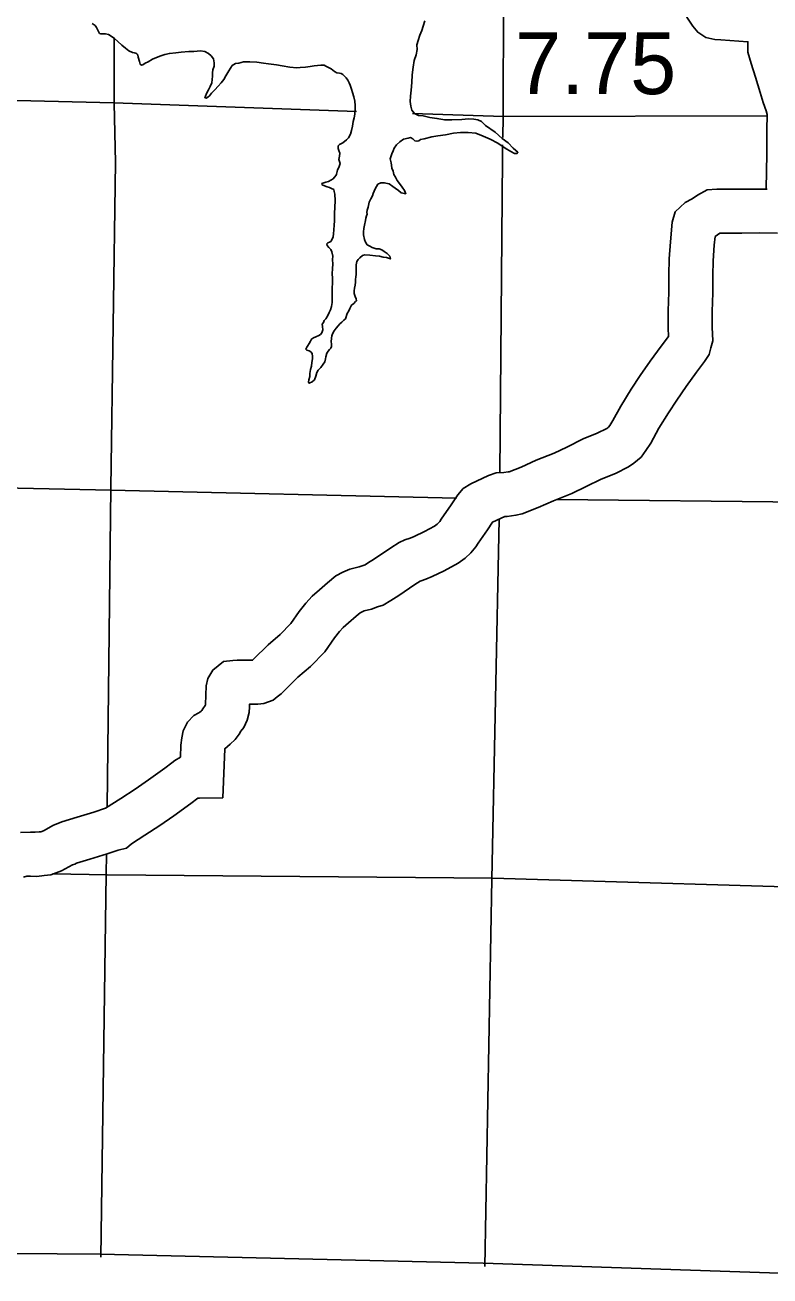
# Model space of a CAD drawing. Extents: x 77230 to 630905, y 790554 to 1662844.
# Drawn here: x 274501 to 284669, y 1532754 to 1549835 of the extents above; entities that cross this region are included whole.
import ezdxf

# ---------------------------------------------------------------- set-up
doc = ezdxf.new("R2010")
doc.units = 0
for name, color, linetype in [('Level 16', 7, 'Continuous'), ('Level 17', 7, 'Continuous'), ('Level 18', 7, 'Continuous'), ('Level 22', 7, 'Continuous'), ('Level 31', 7, 'Continuous')]:
    doc.layers.add(name, color=color, linetype=linetype)

msp = doc.modelspace()

# ---------------------------------------------------------------- linework, layer by layer
at = {"layer": 'Level 16'}
for points in [[(281022, 1548297), (281027, 1548585), (281030, 1550183)], [(275718, 1549654), (275717, 1548768), (275734, 1547959)], [(279023, 1548655), (275711, 1548770), (270417, 1548899), (265076, 1549037), (261346, 1549057)], [(284632, 1548594), (281033, 1548585), (279790, 1548628)], [(281017, 1548018), (281020, 1548199)], [(281017, 1548018), (280981, 1543718)], [(275734, 1547959), (275672, 1543517), (275621, 1539160)], [(265041, 1543701), (270397, 1543598), (275673, 1543482), (280389, 1543376)], [(281762, 1543355), (285132, 1543322)], [(280972, 1543087), (280872, 1538172), (280775, 1532884)], [(275613, 1538514), (275610, 1538239), (275534, 1533012)], [(274881, 1538244), (275622, 1538233), (280881, 1538186), (286111, 1538030), (287282, 1538032)]]:
    msp.add_lwpolyline(points, dxfattribs=at)
at = {"layer": 'Level 17'}
for points in [[(279957, 1549891), (279937, 1549818), (279916, 1549760), (279892, 1549698), (279865, 1549624), (279851, 1549564), (279853, 1549500), (279838, 1549427), (279814, 1549351), (279799, 1549261), (279787, 1549155), (279782, 1549051), (279771, 1548943), (279763, 1548865), (279756, 1548792), (279766, 1548727), (279782, 1548671), (279817, 1548625), (279871, 1548601), (279937, 1548594), (280027, 1548570), (280123, 1548559), (280229, 1548539), (280328, 1548542), (280462, 1548543), (280554, 1548552), (280626, 1548548), (280680, 1548538), (280732, 1548519), (280788, 1548463), (280919, 1548372)], [(276012, 1549450), (275992, 1549456), (275968, 1549460), (275918, 1549483), (275872, 1549517), (275824, 1549561), (275768, 1549609), (275720, 1549650), (275677, 1549684), (275641, 1549706), (275599, 1549716), (275563, 1549715), (275535, 1549713), (275519, 1549719), (275505, 1549747), (275475, 1549803), (275459, 1549827), (275419, 1549854)], [(278786, 1547998), (278795, 1548042), (278797, 1548086), (278785, 1548122), (278775, 1548150), (278775, 1548174), (278776, 1548186), (278794, 1548202), (278838, 1548224), (278890, 1548266), (278914, 1548293), (278945, 1548345), (278957, 1548395), (278971, 1548455), (278982, 1548517), (278994, 1548569), (279002, 1548619), (279007, 1548683), (279005, 1548735), (279001, 1548795), (278990, 1548855), (278972, 1548913), (278958, 1548961), (278941, 1549013), (278923, 1549045), (278907, 1549083), (278883, 1549113), (278863, 1549135), (278839, 1549157), (278817, 1549171), (278793, 1549176), (278759, 1549182), (278725, 1549202), (278680, 1549236), (278644, 1549253), (278608, 1549275), (278582, 1549285), (278538, 1549287), (278492, 1549280), (278446, 1549276), (278393, 1549270), (278327, 1549259), (278255, 1549255), (278209, 1549251), (278117, 1549258), (278009, 1549279), (277935, 1549289), (277823, 1549306), (277755, 1549314), (277663, 1549327), (277571, 1549330), (277485, 1549330), (277421, 1549315), (277374, 1549307), (277328, 1549281), (277284, 1549208), (277241, 1549140), (277213, 1549092), (277179, 1549046), (277138, 1549001), (277092, 1548949), (277048, 1548905), (277017, 1548868), (276995, 1548848), (276973, 1548838), (276957, 1548842), (276963, 1548864), (276980, 1548898), (277004, 1548948), (277028, 1548995), (277050, 1549047), (277057, 1549089), (277061, 1549137), (277061, 1549183), (277066, 1549225), (277082, 1549271), (277082, 1549319), (277074, 1549373), (277043, 1549413), (277007, 1549445), (276955, 1549472), (276897, 1549480), (276805, 1549475), (276735, 1549475), (276634, 1549462), (276558, 1549454), (276472, 1549447), (276410, 1549433), (276356, 1549416), (276296, 1549392), (276239, 1549368), (276181, 1549333), (276141, 1549313), (276109, 1549293), (276089, 1549288), (276073, 1549300), (276061, 1549338), (276047, 1549396), (276039, 1549426), (276028, 1549442), (276012, 1549450)], [(280919, 1548372), (281015, 1548287), (281095, 1548225), (281162, 1548155), (281200, 1548120), (281228, 1548098), (281216, 1548080), (281182, 1548079), (281132, 1548107), (281056, 1548155), (280956, 1548220), (280849, 1548275), (280753, 1548319), (280655, 1548358), (280549, 1548367), (280443, 1548367), (280348, 1548356), (280240, 1548333), (280134, 1548321), (280052, 1548308), (279948, 1548281), (279899, 1548273), (279875, 1548253), (279849, 1548247), (279823, 1548253), (279809, 1548266), (279793, 1548282), (279763, 1548298), (279729, 1548290), (279669, 1548274), (279615, 1548239), (279569, 1548199), (279538, 1548151), (279524, 1548118), (279506, 1548076), (279483, 1548006)], [(278786, 1547998), (278802, 1547942), (278782, 1547888), (278768, 1547857), (278761, 1547835), (278753, 1547799), (278749, 1547785), (278727, 1547755), (278705, 1547733), (278675, 1547715), (278641, 1547698), (278606, 1547690), (278578, 1547678), (278554, 1547670), (278558, 1547652), (278588, 1547640), (278624, 1547624), (278658, 1547616), (278684, 1547602), (278714, 1547587), (278722, 1547563), (278728, 1547525), (278729, 1547493), (278733, 1547469), (278735, 1547444), (278733, 1547414), (278729, 1547364), (278728, 1547324), (278726, 1547282), (278724, 1547248), (278724, 1547214), (278725, 1547160), (278719, 1547102), (278717, 1547036), (278712, 1546982), (278706, 1546941), (278694, 1546911), (278674, 1546881), (278656, 1546869), (278635, 1546861), (278621, 1546849), (278623, 1546825), (278647, 1546797), (278677, 1546771), (278689, 1546737), (278700, 1546679), (278698, 1546635), (278700, 1546569), (278699, 1546509), (278695, 1546439), (278697, 1546378), (278698, 1546310), (278692, 1546244), (278693, 1546174), (278695, 1546096), (278691, 1546044), (278682, 1545992), (278670, 1545947), (278650, 1545909), (278629, 1545861), (278605, 1545825), (278585, 1545799), (278573, 1545775), (278555, 1545750), (278563, 1545720), (278564, 1545674), (278554, 1545630), (278534, 1545610), (278510, 1545594), (278470, 1545577), (278440, 1545565), (278413, 1545547), (278399, 1545517), (278381, 1545487), (278357, 1545450), (278349, 1545438), (278333, 1545408), (278348, 1545396), (278378, 1545387), (278404, 1545371), (278422, 1545351), (278424, 1545307), (278426, 1545277), (278416, 1545229), (278409, 1545176), (278397, 1545132), (278389, 1545076), (278390, 1545034), (278376, 1544992), (278372, 1544960), (278380, 1544944), (278420, 1544962), (278450, 1544992), (278468, 1545039), (278485, 1545091), (278503, 1545123), (278537, 1545157), (278569, 1545204), (278592, 1545236), (278600, 1545278), (278608, 1545304)], [(278608, 1545304), (278622, 1545352), (278639, 1545382), (278655, 1545406), (278675, 1545421), (278685, 1545447), (278685, 1545483), (278681, 1545511), (278686, 1545557), (278688, 1545591), (278698, 1545617), (278720, 1545657), (278747, 1545696), (278775, 1545728), (278797, 1545754), (278825, 1545778), (278851, 1545805), (278875, 1545823), (278900, 1545895), (278920, 1545933), (278936, 1545963), (278957, 1546008), (278987, 1546032), (279013, 1546058), (279025, 1546070), (279021, 1546098), (279005, 1546130), (278994, 1546168), (278994, 1546204), (278998, 1546242), (279006, 1546284), (279012, 1546323), (279013, 1546359), (279017, 1546395), (279019, 1546429), (279021, 1546473), (279022, 1546519), (279022, 1546559), (279032, 1546605), (279050, 1546631), (279073, 1546658), (279105, 1546688), (279141, 1546696), (279207, 1546692), (279283, 1546683), (279337, 1546677), (279389, 1546666), (279433, 1546662), (279489, 1546640), (279479, 1546678), (279443, 1546714), (279405, 1546742), (279373, 1546766), (279333, 1546778), (279295, 1546781), (279241, 1546797), (279208, 1546815), (279172, 1546832), (279146, 1546870), (279136, 1546906), (279122, 1546968), (279123, 1547010), (279127, 1547055), (279133, 1547103), (279146, 1547165), (279154, 1547199), (279164, 1547229), (279172, 1547251), (279166, 1547277), (279170, 1547305), (279183, 1547347), (279197, 1547416), (279219, 1547460), (279242, 1547504), (279254, 1547532), (279268, 1547564), (279278, 1547599), (279296, 1547631), (279317, 1547661), (279357, 1547679), (279403, 1547682), (279469, 1547666), (279519, 1547632), (279552, 1547606), (279600, 1547575), (279636, 1547545), (279698, 1547531), (279680, 1547573), (279649, 1547621), (279611, 1547669), (279581, 1547711), (279557, 1547757), (279536, 1547793), (279526, 1547841), (279508, 1547881), (279502, 1547921), (279499, 1547955), (279483, 1548006)]]:
    msp.add_lwpolyline(points, dxfattribs=at)
at = {"layer": 'Level 18'}
msp.add_lwpolyline([(259715, 1533246), (264915, 1533166), (270250, 1533095), (275526, 1533052), (280755, 1532930), (286011, 1532754), (289923, 1532839)], dxfattribs=at)
at = {"layer": 'Level 22'}
for points in [[(281692, 1550514), (282374, 1550420), (282839, 1550318), (283250, 1550228), (283375, 1550200), (283479, 1550030), (283554, 1549915), (283617, 1549817), (283683, 1549737), (283792, 1549665), (283916, 1549639), (283998, 1549634), (284367, 1549607), (284368, 1549465), (284413, 1549307), (284471, 1549123), (284537, 1548914), (284578, 1548777), (284616, 1548661), (284631, 1548613), (284631, 1548591), (284628, 1548423), (284624, 1548070)], [(284618, 1547603), (284624, 1548070)], [(276622, 1539839), (276628, 1540004), (276640, 1540100), (276659, 1540198), (276718, 1540318), (276806, 1540407), (276873, 1540443), (276887, 1540452), (276904, 1540466), (276915, 1540476), (276930, 1540497), (276961, 1540544), (276965, 1540549), (276966, 1540555), (276971, 1540810), (276997, 1540912), (277062, 1541027), (277210, 1541142), (277335, 1541156), (277397, 1541162), (277607, 1541162), (277620, 1541175), (277820, 1541374), (277985, 1541513), (278127, 1541661), (278244, 1541827), (278334, 1541939), (278420, 1542037), (278522, 1542123), (278631, 1542220), (278742, 1542312), (278838, 1542362), (278935, 1542407), (279061, 1542436), (279118, 1542457), (279142, 1542465), (279176, 1542485), (279270, 1542545), (279494, 1542698), (279609, 1542769), (279685, 1542805), (279758, 1542829), (279812, 1542852), (279954, 1542920), (280092, 1542993), (280126, 1543019), (280149, 1543040), (280163, 1543057), (280181, 1543087), (280319, 1543284), (280410, 1543419), (280480, 1543506), (280585, 1543568), (280826, 1543684), (280931, 1543722), (281036, 1543725), (281095, 1543732), (281111, 1543736), (281275, 1543799), (281479, 1543892), (281723, 1543989), (281897, 1544073), (282118, 1544183), (282311, 1544260), (282441, 1544327), (282457, 1544336), (282466, 1544345), (282481, 1544366), (282526, 1544433), (282633, 1544631), (282776, 1544863), (282899, 1545049), (283033, 1545243), (283182, 1545450), (283284, 1545584), (283281, 1545699), (283281, 1545932), (283288, 1546186), (283288, 1546426), (283295, 1546644), (283310, 1546876), (283334, 1547143), (283375, 1547285), (283512, 1547413), (283606, 1547461), (283681, 1547513), (283811, 1547584), (283943, 1547595), (284047, 1547593), (284286, 1547593), (284526, 1547595), (284632, 1547594)], [(277203, 1539283), (277226, 1539954), (277302, 1540016), (277367, 1540079), (277423, 1540154), (277448, 1540191), (277487, 1540241), (277535, 1540344), (277559, 1540447), (277565, 1540526), (277566, 1540562), (277678, 1540562), (277761, 1540572), (277886, 1540615), (277944, 1540664), (277997, 1540703), (278045, 1540752), (278226, 1540932), (278396, 1541075), (278591, 1541278), (278724, 1541466), (278793, 1541552), (278842, 1541608), (278915, 1541671), (279020, 1541764), (279076, 1541809), (279104, 1541824), (279131, 1541836), (279232, 1541860), (279311, 1541889), (279390, 1541914), (279492, 1541975), (279601, 1542044), (279823, 1542195), (279896, 1542241), (279907, 1542246), (279970, 1542267), (280059, 1542305), (280224, 1542384), (280413, 1542485), (280510, 1542557), (280587, 1542628), (280656, 1542711), (280686, 1542762), (280813, 1542944), (280881, 1543045), (281048, 1543125), (281083, 1543126), (281201, 1543141), (281288, 1543162), (281507, 1543246), (281714, 1543340), (281964, 1543439), (282161, 1543534), (282363, 1543635), (282560, 1543713), (282737, 1543804), (282813, 1543851), (282911, 1543936), (282975, 1544024), (283041, 1544125), (283152, 1544330), (283282, 1544540), (283396, 1544713), (283524, 1544897), (283665, 1545093), (283775, 1545239), (283838, 1545335), (283864, 1545429), (283887, 1545523), (283881, 1545708), (283881, 1545923), (283888, 1546178), (283888, 1546415), (283895, 1546614), (283909, 1546831), (283919, 1546947), (283986, 1546994), (284042, 1546993), (284287, 1546993), (284527, 1546995), (284774, 1546994)], [(274438, 1538808), (274577, 1538815), (274641, 1538812), (274693, 1538818), (274715, 1538820), (274752, 1538833), (274890, 1538909), (274949, 1538933), (275003, 1538955), (275213, 1539019), (275440, 1539088), (275601, 1539141), (275808, 1539275), (276004, 1539403), (276185, 1539530), (276407, 1539687), (276503, 1539762), (276547, 1539793), (276624, 1539836)], [(274479, 1538200), (274525, 1538212), (274577, 1538214), (274661, 1538210), (274761, 1538221), (274851, 1538232), (274998, 1538284), (275150, 1538367), (275179, 1538379), (275205, 1538389), (275386, 1538445), (275622, 1538516), (275774, 1538566), (275884, 1538594), (275952, 1538653), (276135, 1538771), (276341, 1538906), (276530, 1539039), (276766, 1539205), (276858, 1539277), (276883, 1539280), (277203, 1539283)]]:
    msp.add_lwpolyline(points, dxfattribs=at)

# ---------------------------------------------------------------- texts
at = {"layer": 'Level 31'}
msp.add_text('7.75', height=844.8, dxfattribs=at).set_placement((281190, 1548891))

doc.saveas('drawing.dxf')
